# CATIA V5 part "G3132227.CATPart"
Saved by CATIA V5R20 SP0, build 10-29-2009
Part number: G3132227
Revision: 3
Definition: design
Nomenclature: G3132227
Source: made
Description: NOT SPECIFIED
Bounding box of the stored display mesh (mm): x -22 to 27, y -17.322 to 17.322, z -17.5 to 17.5
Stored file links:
  C:\Users\Raffaele\Desktop\3D X SITO CF\BOLEX\24-BUSH REF 313\G3132227.CATPart
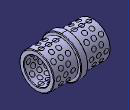
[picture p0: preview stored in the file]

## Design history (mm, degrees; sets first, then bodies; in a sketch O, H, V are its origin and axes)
Body1 "MANIFOLD_SOLID_BREP #11573" (main body)
  Solid1: solid without history
Body2 "MANIFOLD_SOLID_BREP #11724"
  Solid2: solid without history
Body3 "MANIFOLD_SOLID_BREP #11875"
  Solid3: solid without history
Body4 "MANIFOLD_SOLID_BREP #12026"
  Solid4: solid without history
Body5 "MANIFOLD_SOLID_BREP #12177"
  Solid5: solid without history
Body6 "MANIFOLD_SOLID_BREP #12326"
  Solid6: solid without history
Body7 "MANIFOLD_SOLID_BREP #12475"
  Solid7: solid without history
Body8 "MANIFOLD_SOLID_BREP #12624"
  Solid8: solid without history
Body9 "MANIFOLD_SOLID_BREP #12773"
  Solid9: solid without history
Body10 "MANIFOLD_SOLID_BREP #12922"
  Solid10: solid without history
Body11 "MANIFOLD_SOLID_BREP #13071"
  Solid11: solid without history
Body12 "MANIFOLD_SOLID_BREP #13220"
  Solid12: solid without history
Body13 "MANIFOLD_SOLID_BREP #13369"
  Solid13: solid without history
Body14 "MANIFOLD_SOLID_BREP #13518"
  Solid14: solid without history
Body15 "MANIFOLD_SOLID_BREP #13667"
  Solid15: solid without history
Body16 "MANIFOLD_SOLID_BREP #13816"
  Solid16: solid without history
Body17 "MANIFOLD_SOLID_BREP #13965"
  Solid17: solid without history
Body18 "MANIFOLD_SOLID_BREP #14114"
  Solid18: solid without history
Body19 "MANIFOLD_SOLID_BREP #14263"
  Solid19: solid without history
Body20 "MANIFOLD_SOLID_BREP #14412"
  Solid20: solid without history
Body21 "MANIFOLD_SOLID_BREP #14561"
  Solid21: solid without history
Body22 "MANIFOLD_SOLID_BREP #14710"
  Solid22: solid without history
Body23 "MANIFOLD_SOLID_BREP #14859"
  Solid23: solid without history
Body24 "MANIFOLD_SOLID_BREP #15008"
  Solid24: solid without history
Body25 "MANIFOLD_SOLID_BREP #15157"
  Solid25: solid without history
Body26 "MANIFOLD_SOLID_BREP #15306"
  Solid26: solid without history
Body27 "MANIFOLD_SOLID_BREP #15455"
  Solid27: solid without history
Body28 "MANIFOLD_SOLID_BREP #15604"
  Solid28: solid without history
Body29 "MANIFOLD_SOLID_BREP #15753"
  Solid29: solid without history
Body30 "MANIFOLD_SOLID_BREP #15902"
  Solid30: solid without history
Body31 "MANIFOLD_SOLID_BREP #16051"
  Solid31: solid without history
Body32 "MANIFOLD_SOLID_BREP #16202"
  Solid32: solid without history
Body33 "MANIFOLD_SOLID_BREP #16353"
  Solid33: solid without history
Body34 "MANIFOLD_SOLID_BREP #16502"
  Solid34: solid without history
Body35 "MANIFOLD_SOLID_BREP #16651"
  Solid35: solid without history
Body36 "MANIFOLD_SOLID_BREP #16800"
  Solid36: solid without history
Body37 "MANIFOLD_SOLID_BREP #16949"
  Solid37: solid without history
Body38 "MANIFOLD_SOLID_BREP #17098"
  Solid38: solid without history
Body39 "MANIFOLD_SOLID_BREP #17247"
  Solid39: solid without history
Body40 "MANIFOLD_SOLID_BREP #17396"
  Solid40: solid without history
Body41 "MANIFOLD_SOLID_BREP #17545"
  Solid41: solid without history
Body42 "MANIFOLD_SOLID_BREP #17694"
  Solid42: solid without history
Body43 "MANIFOLD_SOLID_BREP #17843"
  Solid43: solid without history
Body44 "MANIFOLD_SOLID_BREP #17992"
  Solid44: solid without history
Body45 "MANIFOLD_SOLID_BREP #18141"
  Solid45: solid without history
Body46 "MANIFOLD_SOLID_BREP #18290"
  Solid46: solid without history
Body47 "MANIFOLD_SOLID_BREP #18439"
  Solid47: solid without history
Body48 "MANIFOLD_SOLID_BREP #18588"
  Solid48: solid without history
Body49 "MANIFOLD_SOLID_BREP #18737"
  Solid49: solid without history
Body50 "MANIFOLD_SOLID_BREP #18886"
  Solid50: solid without history
Body51 "MANIFOLD_SOLID_BREP #19035"
  Solid51: solid without history
Body52 "MANIFOLD_SOLID_BREP #19184"
  Solid52: solid without history
Body53 "MANIFOLD_SOLID_BREP #19333"
  Solid53: solid without history
Body54 "MANIFOLD_SOLID_BREP #19482"
  Solid54: solid without history
Body55 "MANIFOLD_SOLID_BREP #19631"
  Solid55: solid without history
Body56 "MANIFOLD_SOLID_BREP #19780"
  Solid56: solid without history
Body57 "MANIFOLD_SOLID_BREP #19929"
  Solid57: solid without history
Body58 "MANIFOLD_SOLID_BREP #20078"
  Solid58: solid without history
Body59 "MANIFOLD_SOLID_BREP #20227"
  Solid59: solid without history
Body60 "MANIFOLD_SOLID_BREP #20378"
  Solid60: solid without history
Body61 "MANIFOLD_SOLID_BREP #20529"
  Solid61: solid without history
Body62 "MANIFOLD_SOLID_BREP #20680"
  Solid62: solid without history
Body63 "MANIFOLD_SOLID_BREP #20831"
  Solid63: solid without history
Body64 "MANIFOLD_SOLID_BREP #20982"
  Solid64: solid without history
Body65 "MANIFOLD_SOLID_BREP #21133"
  Solid65: solid without history
Body66 "MANIFOLD_SOLID_BREP #21282"
  Solid66: solid without history
Body67 "MANIFOLD_SOLID_BREP #21431"
  Solid67: solid without history
Body68 "MANIFOLD_SOLID_BREP #21580"
  Solid68: solid without history
Body69 "MANIFOLD_SOLID_BREP #21729"
  Solid69: solid without history
Body70 "MANIFOLD_SOLID_BREP #21878"
  Solid70: solid without history
Body71 "MANIFOLD_SOLID_BREP #22027"
  Solid71: solid without history
Body72 "MANIFOLD_SOLID_BREP #22176"
  Solid72: solid without history
Body73 "MANIFOLD_SOLID_BREP #22325"
  Solid73: solid without history
Body74 "MANIFOLD_SOLID_BREP #22474"
  Solid74: solid without history
Body75 "MANIFOLD_SOLID_BREP #22623"
  Solid75: solid without history
Body76 "MANIFOLD_SOLID_BREP #22772"
  Solid76: solid without history
Body77 "MANIFOLD_SOLID_BREP #22921"
  Solid77: solid without history
Body78 "MANIFOLD_SOLID_BREP #23070"
  Solid78: solid without history
Body79 "MANIFOLD_SOLID_BREP #23219"
  Solid79: solid without history
Body80 "MANIFOLD_SOLID_BREP #23368"
  Solid80: solid without history
Body81 "MANIFOLD_SOLID_BREP #23517"
  Solid81: solid without history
